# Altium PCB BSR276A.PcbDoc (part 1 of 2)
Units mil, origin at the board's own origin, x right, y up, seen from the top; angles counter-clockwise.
Board outline 2517.71 x 2251 mil, 4 copper layers (Top Layer, Signal Layer 1, Signal Layer 2, Bottom Layer), stack 61.6 mil thick; 70 components, 21 nets, 118 pads, 66 vias.
Unrouted connection lines stored in the file: 1.
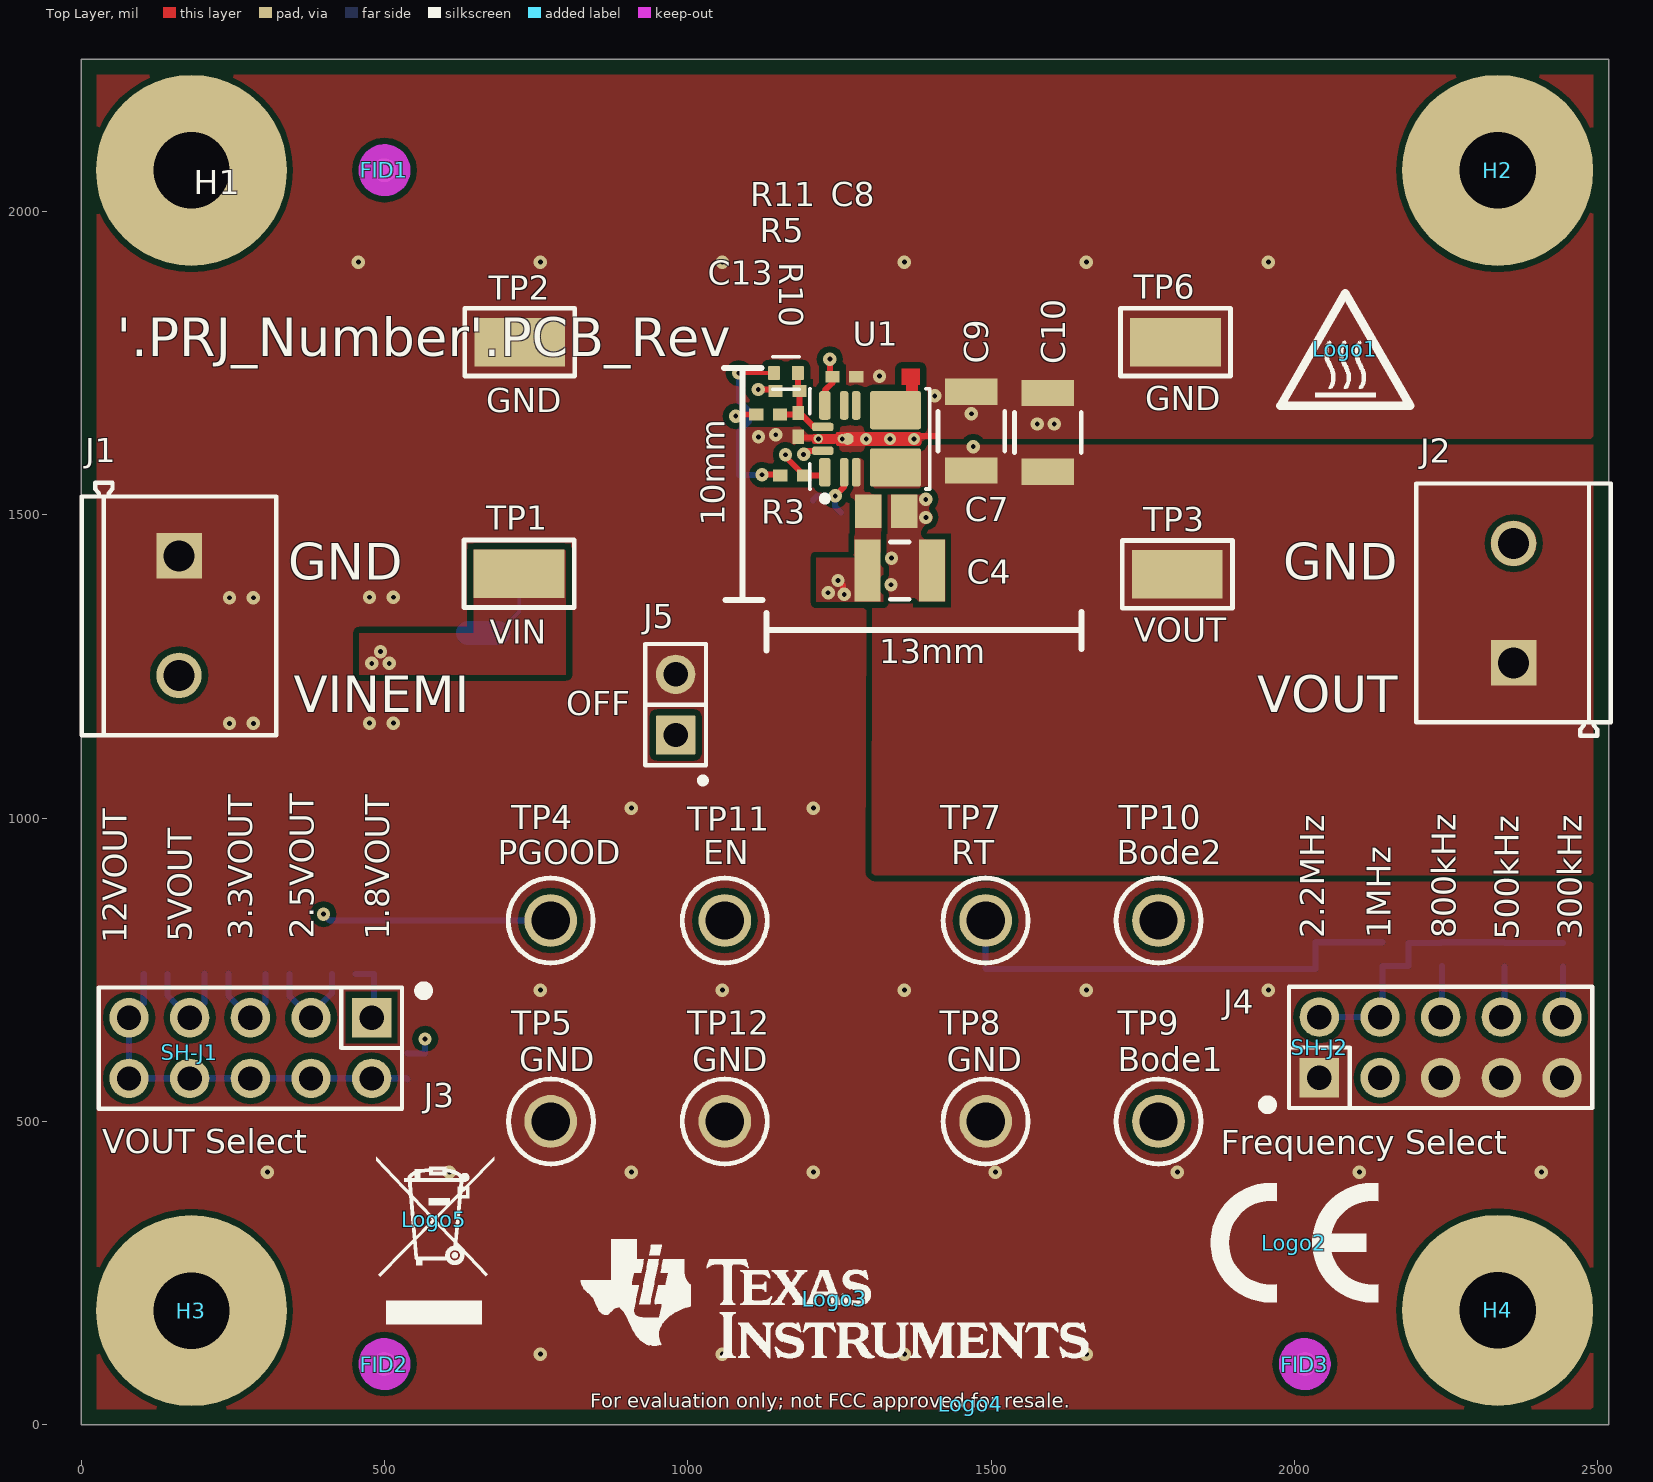
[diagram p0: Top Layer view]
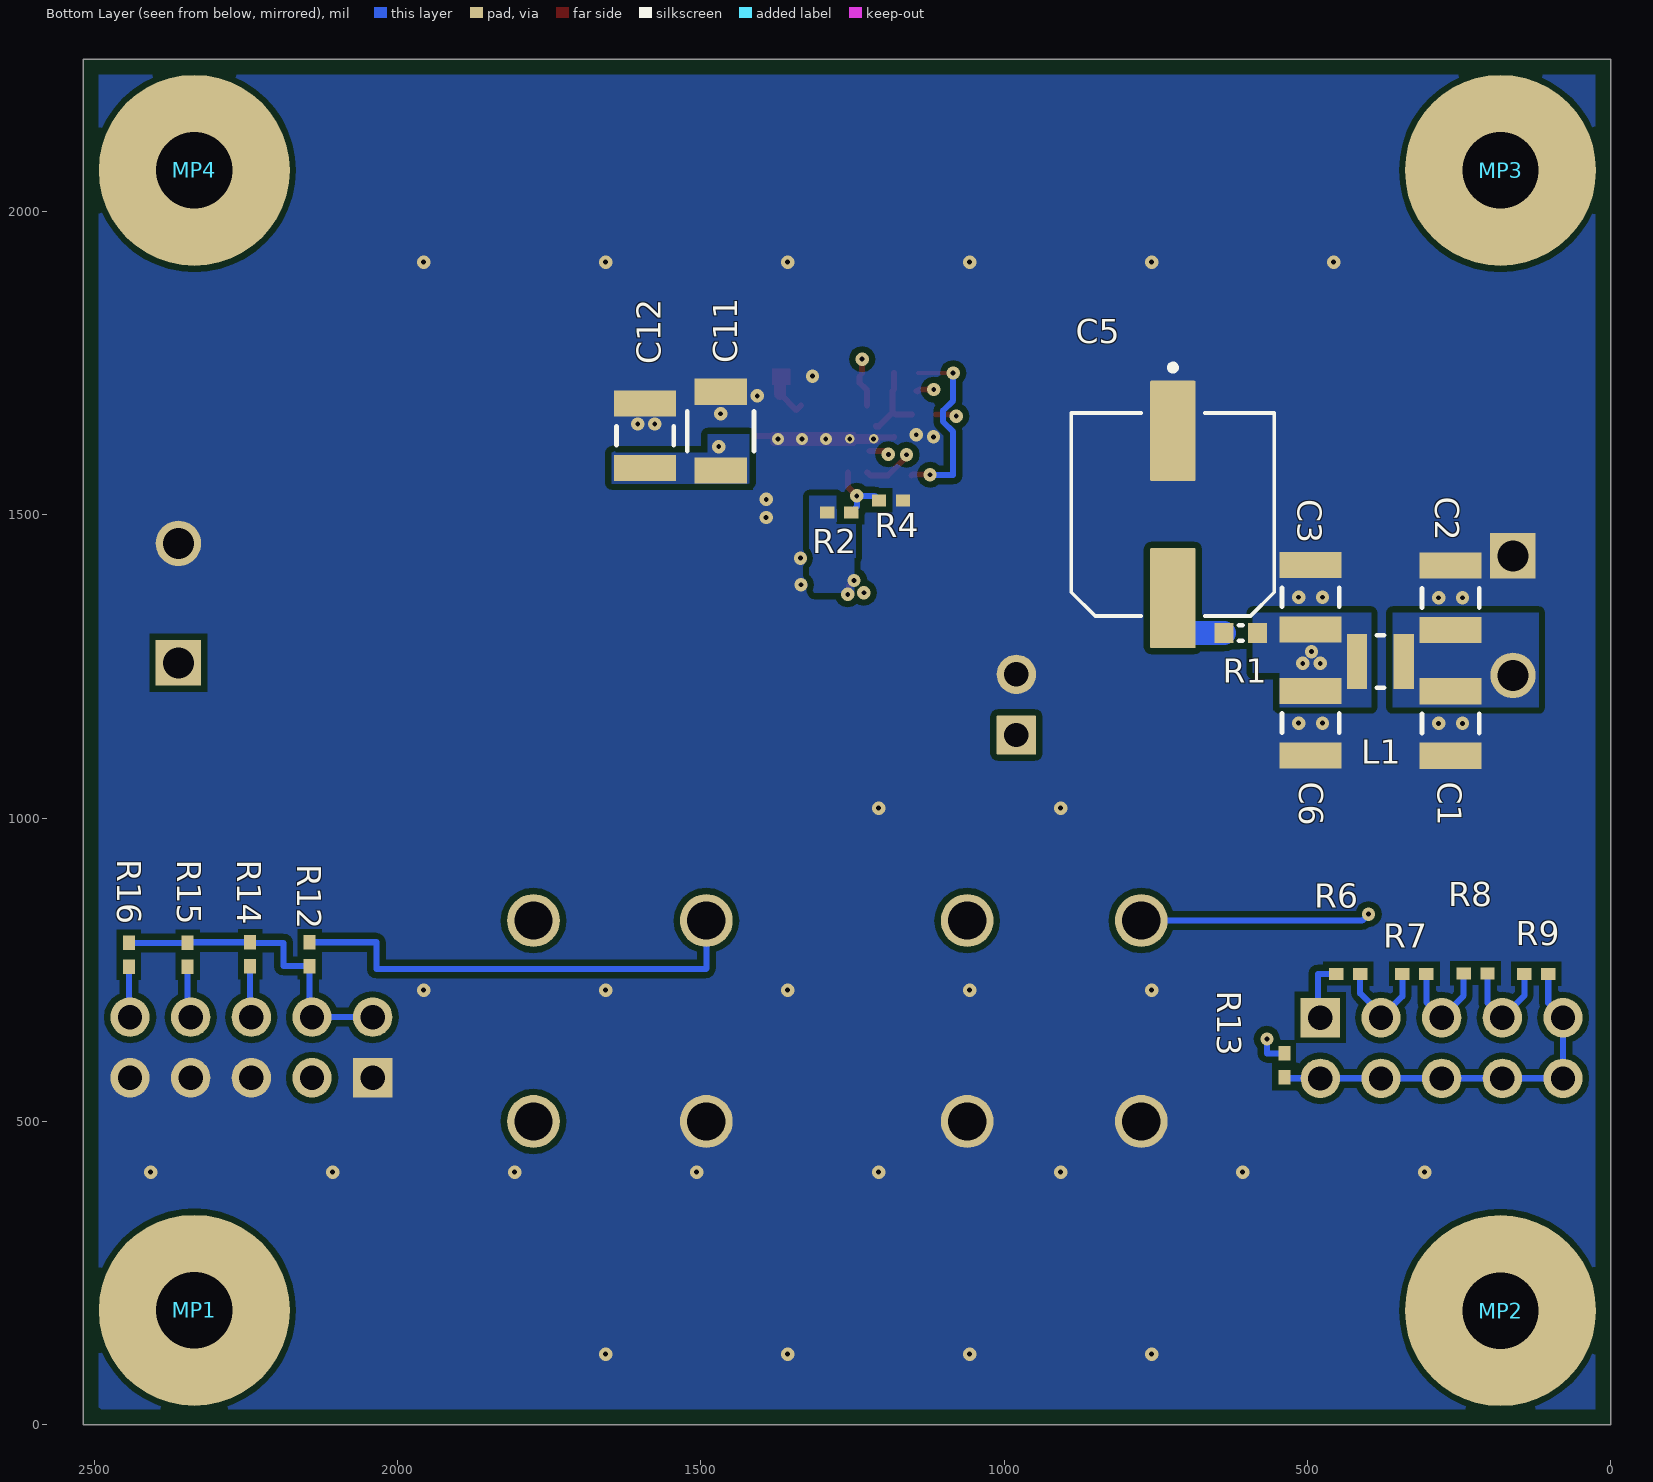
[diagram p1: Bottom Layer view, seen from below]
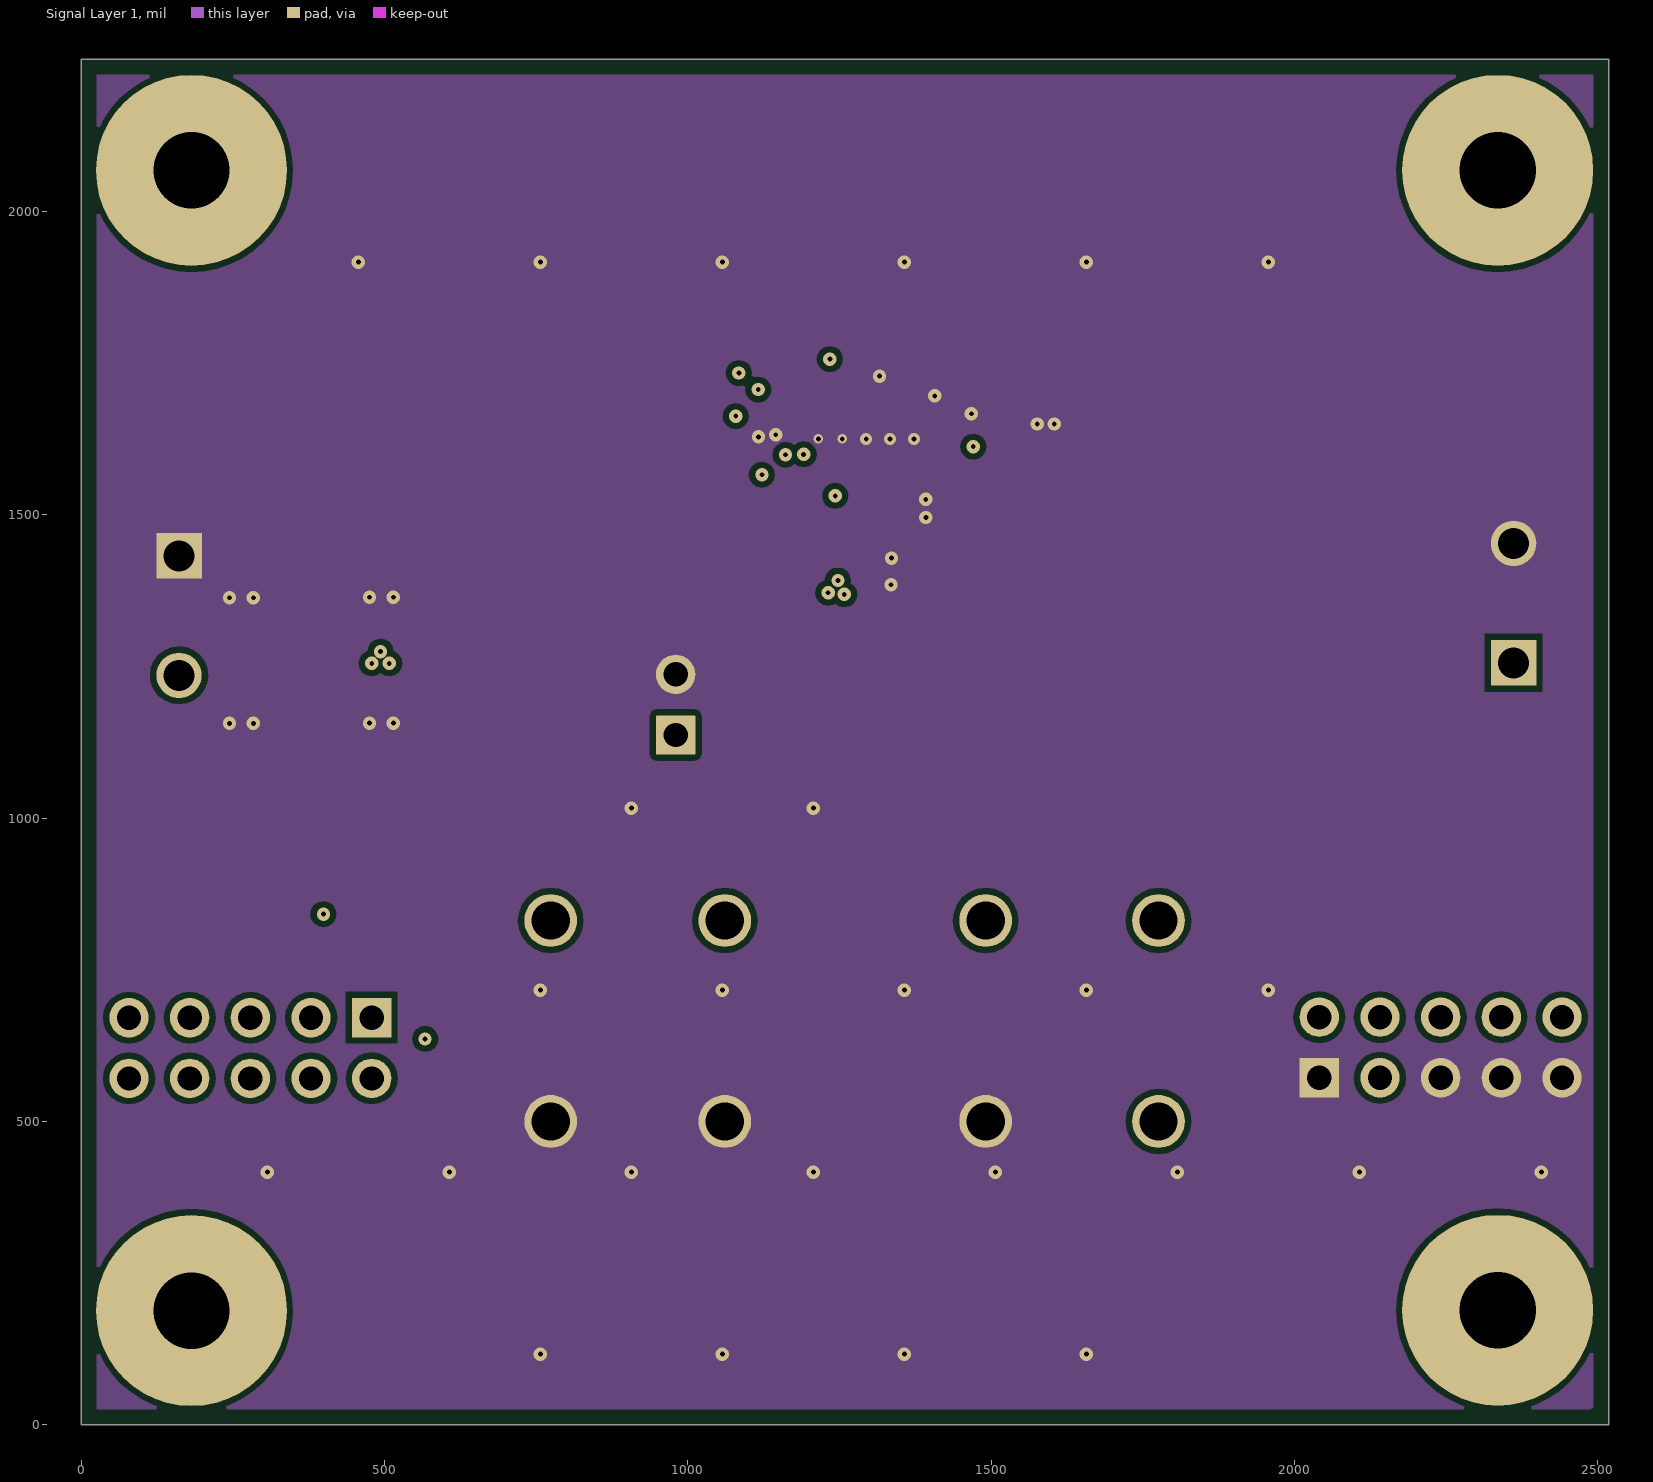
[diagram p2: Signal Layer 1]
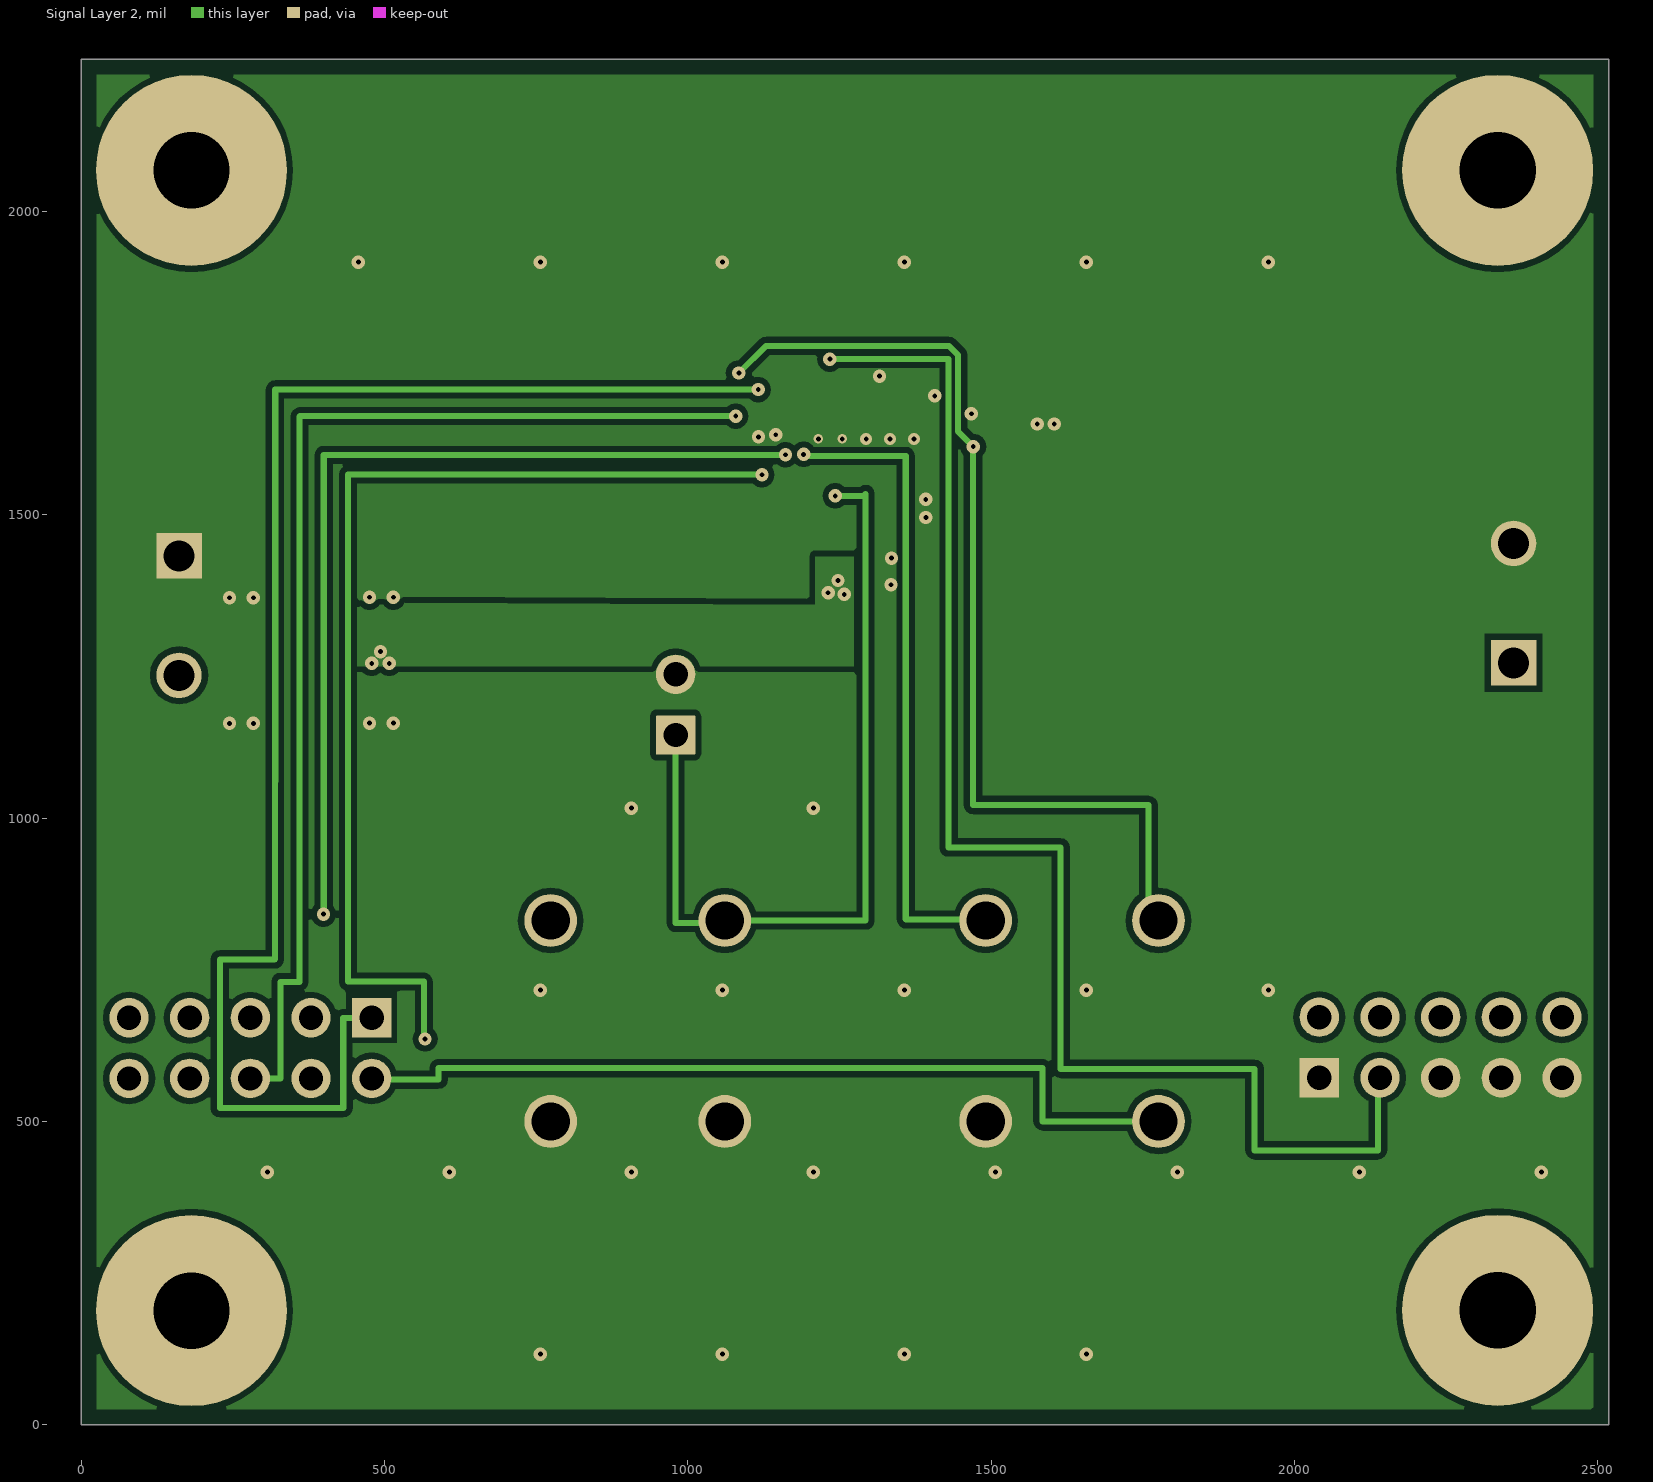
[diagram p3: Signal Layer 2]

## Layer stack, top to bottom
Top Solder: solder mask 0.4, Solder Resist, Dk 3.5
Top Layer: signal copper 1.4
Dielectric 1: prepreg 8, FR-4 High Tg, Dk 4.2
Signal Layer 1: signal copper 1.4
Dielectric 2: core 40, FR-4 High Tg, Dk 4.2
Signal Layer 2: signal copper 1.4
Dielectric 3: prepreg 8, FR-4 High Tg, Dk 4.2
Bottom Layer: signal copper 1.4
Bottom Solder: solder mask 0.4, Solder Resist, Dk 3.5

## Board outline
0,0 2517.71,0 2517.71,2251 2517.69,2250.98 0,2250.98

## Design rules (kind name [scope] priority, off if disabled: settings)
AcuteAngle [All] p1: minimum=4.50000000000000E+0001 checktracksonly=FALSE
AssemblyTestPointUsage [All] p1: valid=2
BoardOutlineClearance BoardOutlineClearance_MountingHoles [OnCopper and InComponentClass('Mounting Holes')] p1: gap=39.37 ignorepadtopadclearanceinfootprint=FALSE
BoardOutlineClearance BoardOutlineClearance_Poly [OnCopper and IsPoly] p2: gap=25 ignorepadtopadclearanceinfootprint=FALSE
BoardOutlineClearance [OnCopper and Not InComponentClass('Logo') and not InComponentClass('FiducialMark') and not InRegion(1000,500,4000,800) and not InPoly] p3: gap=40 ignorepadtopadclearanceinfootprint=FALSE
Clearance Clearance_Keepouts [((IsTrack Or IsArc) And Not InPoly) And IsFree and IsKeepOut vs ((IsTrack Or IsArc) And Not InPoly) And IsFree and IsKeepOut] p1: gap=0 ignorepadtopadclearanceinfootprint=FALSE
Clearance Clearance_Poly [InPolygon] p2: gap=10 ignorepadtopadclearanceinfootprint=TRUE
Clearance Clearance_FiducialMark [IsKeepOut and InComponentClass('FiducialMark') vs IsPad and InComponentClass('FiducialMark')] p3: gap=0 ignorepadtopadclearanceinfootprint=FALSE
Clearance [All] p4: gap=5.91 ignorepadtopadclearanceinfootprint=TRUE except(7.87: Text-Text Text-Hole)
ComponentClearance ComponentClearance_MountingHoles_FiducialMarks [InComponentClass('Mounting Holes') vs InComponentClass('FiducialMark')] p1: gap=50 collisioncheckmode=3 verticalgap=10 showdistances=FALSE
ComponentClearance ComponentClearance_Shunt [InComponentClass('Header') vs InComponentClass('Shunt')] p2: gap=0 collisioncheckmode=3 verticalgap=0 showdistances=FALSE
ComponentClearance ComponentClearance_Logo [InComponentClass('Logo')] p3: gap=30 collisioncheckmode=3 verticalgap=10 showdistances=FALSE
ComponentClearance ComponentClearance_ScrewToNut [(HasFootprint('NY PMS 440 0025 PH')) vs (HasFootprint('Keystone_1902C'))] p4: gap=5 collisioncheckmode=3 verticalgap=10 showdistances=FALSE
ComponentClearance ComponentClearance_MountingHoles [InComponentClass('Mounting Holes')] p5: gap=100 collisioncheckmode=3 verticalgap=100000 showdistances=FALSE
ComponentClearance ComponentClearance_SmallPassives [HasFootprint('0201*') or HasFootprint('0402*') or HasFootprint('0508') or HasFootprint('0603*') or HasFootprint('0612') or HasFootprint('0805*') or HasFootprint('0815*') or HasFootprint('0830*') or HasFootprint('1206*') or HasFootprint('1210*') or HasFootprint('1808*') or HasFootprint('1812*') or HasFootprint('1825*') or HasFootprint('2010*') or HasFootprint('2220*') or HasFootprint('2225*') or HasFootprint('2512*') or HasFootprint('2728*') or HasFootprint('3518*') vs HasFootprint('0201*') or HasFootprint('0402*') or HasFootprint('0508') or HasFootprint('0603*') or HasFootprint('0612') or HasFootprint('0805*') or HasFootprint('0815*') or HasFootprint('0830*') or HasFootprint('1206*') or HasFootprint('1210*') or HasFootprint('1808*') or HasFootprint('1812*') or HasFootprint('1825*') or HasFootprint('2010*') or HasFootprint('2220*') or HasFootprint('2225*') or HasFootprint('2512*') or HasFootprint('2728*') or HasFootprint('3518*')] p6: gap=14.96 collisioncheckmode=3 verticalgap=10 showdistances=FALSE
ComponentClearance ComponentClearance_THtoSMT [IsThruComponent vs IsSMTComponent] p7: gap=30 collisioncheckmode=3 verticalgap=30 showdistances=FALSE
ComponentClearance ComponentClearance_THtoTH [IsThruComponent vs IsThruComponent] p8: gap=20 collisioncheckmode=3 verticalgap=30 showdistances=FALSE
ComponentClearance [All] p9: gap=8 collisioncheckmode=3 verticalgap=10 showdistances=FALSE
DiffPairsRouting [All] p1: maxlimit=100 minlimit=10 mostfreqgap=10 substack1={4869F302-31FF-4282-8A62-242DEF238AA7} toplayer_{4869f302-31ff-4282-8a62-242def238aa7}_minwidth=15 toplayer_{4869f302-31ff-4282-8a62-242def238aa7}_maxwidth=15 toplayer_{4869f302-31ff-4282-8a62-242def238aa7}_prefwidth=15 midlayer1_{4869f302-31ff-4282-8a62-242def238aa7}_minwidth=15 midlayer1_{4869f302-31ff-4282-8a62-242def238aa7}_maxwidth=15 midlayer1_{4869f302-31ff-4282-8a62-242def238aa7}_prefwidth=15 midlayer2_{4869f302-31ff-4282-8a62-242def238aa7}_minwidth=15 midlayer2_{4869f302-31ff-4282-8a62-242def238aa7}_maxwidth=15 midlayer2_{4869f302-31ff-4282-8a62-242def238aa7}_prefwidth=15 bottomlayer_{4869f302-31ff-4282-8a62-242def238aa7}_minwidth=15 bottomlayer_{4869f302-31ff-4282-8a62-242def238aa7}_maxwidth=15 bottomlayer_{4869f302-31ff-4282-8a62-242def238aa7}_prefwidth=15 toplayer_minwidth=15 toplayer_maxwidth=15 toplayer_prefwidth=15 midlayer1_minwidth=15 midlayer1_maxwidth=15 midlayer1_prefwidth=15 midlayer2_minwidth=15 midlayer2_maxwidth=15 midlayer2_prefwidth=15 bottomlayer_minwidth=15 bottomlayer_maxwidth=15 bottomlayer_prefwidth=15 substack2={E3C2131B-1C0E-431A-9B14-2B1FF8BF5809} toplayer_{e3c2131b-1c0e-431a-9b14-2b1ff8bf5809}_minwidth=15 toplayer_{e3c2131b-1c0e-431a-9b14-2b1ff8bf5809}_maxwidth=15 toplayer_{e3c2131b-1c0e-431a-9b14-2b1ff8bf5809}_prefwidth=15 midlayer1_{e3c2131b-1c0e-431a-9b14-2b1ff8bf5809}_minwidth=15 midlayer1_{e3c2131b-1c0e-431a-9b14-2b1ff8bf5809}_maxwidth=15 midlayer1_{e3c2131b-1c0e-431a-9b14-2b1ff8bf5809}_prefwidth=15 midlayer2_{e3c2131b-1c0e-431a-9b14-2b1ff8bf5809}_minwidth=15 midlayer2_{e3c2131b-1c0e-431a-9b14-2b1ff8bf5809}_maxwidth=15 midlayer2_{e3c2131b-1c0e-431a-9b14-2b1ff8bf5809}_prefwidth=15 bottomlayer_{e3c2131b-1c0e-431a-9b14-2b1ff8bf5809}_minwidth=15 bottomlayer_{e3c2131b-1c0e-431a-9b14-2b1ff8bf5809}_maxwidth=15 bottomlayer_{e3c2131b-1c0e-431a-9b14-2b1ff8bf5809}_prefwidth=15 substack3={6311EC87-DE6E-4A89-91EC-D127DB06BA4F} toplayer_{6311ec87-de6e-4a89-91ec-d127db06ba4f}_minwidth=15 toplayer_{6311ec87-de6e-4a89-91ec-d127db06ba4f}_maxwidth=15 toplayer_{6311ec87-de6e-4a89-91ec-d127db06ba4f}_prefwidth=15 midlayer1_{6311ec87-de6e-4a89-91ec-d127db06ba4f}_minwidth=15 midlayer1_{6311ec87-de6e-4a89-91ec-d127db06ba4f}_maxwidth=15 midlayer1_{6311ec87-de6e-4a89-91ec-d127db06ba4f}_prefwidth=15 midlayer2_{6311ec87-de6e-4a89-91ec-d127db06ba4f}_minwidth=15 midlayer2_{6311ec87-de6e-4a89-91ec-d127db06ba4f}_maxwidth=15 midlayer2_{6311ec87-de6e-4a89-91ec-d127db06ba4f}_prefwidth=15 bottomlayer_{6311ec87-de6e-4a89-91ec-d127db06ba4f}_minwidth=15 bottomlayer_{6311ec87-de6e-4a89-91ec-d127db06ba4f}_maxwidth=15 bottomlayer_{6311ec87-de6e-4a89-91ec-d127db06ba4f}_prefwidth=15 substack4={011EBE24-0305-46D9-879A-9FB90939BB7C} toplayer_{011ebe24-0305-46d9-879a-9fb90939bb7c}_minwidth=15 toplayer_{011ebe24-0305-46d9-879a-9fb90939bb7c}_maxwidth=15 toplayer_{011ebe24-0305-46d9-879a-9fb90939bb7c}_prefwidth=15 midlayer1_{011ebe24-0305-46d9-879a-9fb90939bb7c}_minwidth=15 midlayer1_{011ebe24-0305-46d9-879a-9fb90939bb7c}_maxwidth=15 midlayer1_{011ebe24-0305-46d9-879a-9fb90939bb7c}_prefwidth=15 midlayer2_{011ebe24-0305-46d9-879a-9fb90939bb7c}_minwidth=15 midlayer2_{011ebe24-0305-46d9-879a-9fb90939bb7c}_maxwidth=15 midlayer2_{011ebe24-0305-46d9-879a-9fb90939bb7c}_prefwidth=15 bottomlayer_{011ebe24-0305-46d9-879a-9fb90939bb7c}_minwidth=15 bottomlayer_{011ebe24-0305-46d9-879a-9fb90939bb7c}_maxwidth=15 bottomlayer_{011ebe24-0305-46d9-879a-9fb90939bb7c}_prefwidth=15 maxuncoupledlength=1000
FabricationTestPointUsage TestPointUsage [All] p1: valid=2 allowmultiple=FALSE
FabricationTestpoint Testpoint [All] p1: side=3 testpointundercomponent=TRUE minsize=40 maxsize=100 preferedsize=60 minholesize=0 maxholesize=40 preferedholesize=32 testpointgrid=1 allowsidetop=TRUE allowsidebottom=TRUE usegrid=TRUE gridtolerance=0.01
FanoutControl Fanout_LCC [IsLCC] p1: bgadir=Out bgaviamode=Centered fanoutstyle=Auto fanoutdirection=Alternating viagrid=1 // Fanout_LCC (Default Rule)
FanoutControl Fanout_BGA [IsBGA] p2: bgadir=Out bgaviamode=Centered fanoutstyle=Auto fanoutdirection=Alternating viagrid=1 // Fanout_BGA (Default Rule)
FanoutControl Fanout_Default [All] p4: bgadir=Out bgaviamode=Centered fanoutstyle=Auto fanoutdirection=Alternating viagrid=1 // Fanout_Default (Default Rule)
FanoutControl Fanout_Small [(CompPinCount < 5)] p5: bgadir=Out bgaviamode=Centered fanoutstyle=Auto fanoutdirection=OutThenIn viagrid=1 // Fanout_Small (Default Rule)
HoleSize [All] p1: absolutevalues=TRUE maxlimit=251 minlimit=7.87 maxpercent=80.000 minpercent=20.000
MinimumAnnularRing MinimumAnnularRing_ThermalPadVias [IsVia and InAnyComponent] p1: minimumring=5.91
MinimumAnnularRing [All] p2: minimumring=5.9
MinimumSolderMaskSliver MinimumSolderMaskSliver_Logo [InComponentClass('Logo') vs InComponentClass('Logo')] p1: minsoldermaskwidth=0.7
MinimumSolderMaskSliver [All] p2: minsoldermaskwidth=3.94
PlaneConnect [All] p1: planeconnectstyle=Relief reliefexpansion=10 reliefentries=4 reliefconductorwidth=10 reliefairgap=10
PolygonConnect [All] p1: connectstyle=Direct reliefconductorwidth=10 reliefentries=4 polygonreliefangle="90 Angle" airgapwidth=10
RoutingLayers [All] p1: top layer_v5=TRUE mid layer 1_v5=FALSE mid layer 2_v5=FALSE bottom layer_v5=TRUE
RoutingVias ThermalPadVias [IsVia and InAnyComponent] p1: holewidth=7.87 width=19.68 viastyle="Through Hole" minholewidth=7.87 minwidth=19.68 maxholewidth=12.99 maxwidth=23.62
RoutingVias [All] p2: holewidth=16 width=34 viastyle="Through Hole" minholewidth=7.87 minwidth=24 maxholewidth=40 maxwidth=65
SilkToBoardRegionClearance [Not ((IsComment or IsDesignator) And (Hide <> 'False')) and not InRegion(1000,500,4000,800)] p1:
SilkToSilkClearance SilkToSilkClearance_Pb-FreeLogo [(HasFootprint('Pb-Free_Overlay_Medium') OR HasFootprint('Pb-Free_Overlay_Small')) vs (HasFootprint('Pb-Free_Overlay_Medium') OR HasFootprint('Pb-Free_Overlay_Small'))] p1: silktosilkclearance=0
SilkToSilkClearance [All] p2: silktosilkclearance=3.94
SilkToSolderMaskClearance SilkToComponentPadClearance [(IsPad or IsFill or IsRegion) and InAnycomponent] p1: minsilkscreentomaskgap=5 clearancetoexposedcopper=TRUE
SilkToSolderMaskClearance "Silk to Solder Mask Opening" [All] p2: minsilkscreentomaskgap=3.94 clearancetoexposedcopper=FALSE
SolderMaskExpansion [All] p1: expansion=1.97 istentingtop=FALSE
UnRoutedNet [All] p1: checkbadconnections=TRUE
Width [All] p1: maxlimit=100 minlimit=6 preferedwidth=10 substack1={4869F302-31FF-4282-8A62-242DEF238AA7} substack2={E3C2131B-1C0E-431A-9B14-2B1FF8BF5809} substack3={6311EC87-DE6E-4A89-91EC-D127DB06BA4F} substack4={011EBE24-0305-46D9-879A-9FB90939BB7C} checkconnectedcopper=TRUE
13 further rules are at their usual default settings.

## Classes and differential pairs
component class AssemblyNote: ZZ1 ZZ2 ZZ3 ZZ4
component class FiducialMark: FID1 FID2 FID3
component class BSR276A_Hardware: FID1 FID2 FID3 H1 H2 H3 H4 Logo1 Logo2 Logo3 Logo4 Logo5 MP1 MP2 MP3 MP4 SH-J1 SH-J2 ZZ1 ZZ2 ZZ3 ZZ4
component class Logo: Logo3
component class "Mounting Holes": H1 H2 H3 H4
component class BSR276A: C1 C2 C3 C4 C5 C6 C7 C8 C9 C10 C11 C12 C13 J1 J2 J3 J4 J5 L1 R1 R2 R3 R4 R5 R6 R7 R8 R9 R10 R11 R12 R13 R14 R15 R16 TP1 TP2 TP3 TP4 TP5 TP6 TP7 TP8 TP9 TP10 TP11 TP12 U1
component class Header: J3 J4 J5

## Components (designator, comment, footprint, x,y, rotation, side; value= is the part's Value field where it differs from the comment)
C1 "CGA6N3X7R2A225K230AB" 1210_250L 264.24,1156 r270 bottom value=2.2uF
C2 "CGA6N3X7R2A225K230AB" 1210_250L 264.24,1363 r90 bottom value=2.2uF
C3 "CGA6N3X7R2A225K230AB" 1210_250L 495,1364.01 r90 bottom value=2.2uF
C4 "CGA6N3X7R2A225K230AB" 1210_250L 1349.42,1407.93 r0 top value=2.2uF
C5 "875075955001" FP-875075955001_SMT_CAP_8MM3_8MM3-MFG 722,1500.35 r270 bottom value=10µF
C6 "CGA6N3X7R2A225K230AB" 1210_250L 495,1156.38 r270 bottom value=2.2uF
C7 "885012207128" 0805L 1327.23,1505.64 r0 top value=0.1uF
C8 "EMK105BJ105KVHF" 0402L 1258.28,1727.36 r180 top value=1uF
C9 "CGA6P1X7R1C226M250AC" 1210_280 1467.52,1637.8 r90 top value=22uF
C10 "CGA6P1X7R1C226M250AC" 1210_280 1593.5,1635.63 r90 top value=22uF
C11 "CGA6P1X7R1C226M250AC" 1210_280 1467.52,1637.79 r90 bottom value=22uF
C12 "GRM32EC70J107ME15L" 1210_270L 1592,1630.05 r90 bottom value=100uF
C13 "CGA2B2NP01H220J050BA" 0402L 1132.48,1664.86 r0 top value=22pF
FID1 "Fiducial" Fiducial10-20 500,2067.83 r0 top
FID2 "Fiducial" Fiducial10-20 500,100 r0 top
FID3 "Fiducial" Fiducial10-20 2017,100 r0 top
H1 "NY PMS 440 0025 PH" "NY PMS 440 0025 PH"#1 182,2067.57 r0 top
H2 "NY PMS 440 0025 PH" "NY PMS 440 0025 PH"#1 2335,2067.57 r0 top
H3 "NY PMS 440 0025 PH" "NY PMS 440 0025 PH"#2 182,188.57 r0 top
H4 "NY PMS 440 0025 PH" "NY PMS 440 0025 PH"#3 2334.65,188.57 r0 top
J1 "VIN" Phoenix_1729018 161.42,1333.66 r270 top
J2 "VOUT" Phoenix_1729018 2361.22,1354.33 r90 top
J3 "VOUT Select" CONN_PEC05DAAN 279,620.87 r180 top
J4 "Frequency Select" CONN_PEC05DAAN 2241,621.85 r0 top
J5 "OFF" Samtec_HTSW-102-07-G-S 980,1186.81 r90 top
L1 "74438324047" WE-MAPI_2512 380,1258 r0 bottom value=4.7uH
Logo1 "CAUTION HOT SURFACE" IEC_HotSurface_Small 2084,1772.64 r0 top
Logo2 "CE Mark" CE_Mark_5mm 2000,300 r0 top
Logo3 "Texas Instruments" TI_Stacked_Overlay_Small 1242.13,207.68 r0 top
Logo4 "FCC disclaimer" FCC_disclaimer 1466.41,33.46 r0 top
Logo5 "WEEE logo" WEEE_Minimum 582,337.6 r0 top
MP1 "1902D_Ndrill" FP-1902D_Ndrill_HEX_STANDOFF-MFG 2335,188.57 r180 bottom
MP2 "1902D_Ndrill" FP-1902D_Ndrill_HEX_STANDOFF-MFG 182,188.05 r180 bottom
MP3 "1902D_Ndrill" FP-1902D_Ndrill_HEX_STANDOFF-MFG 182,2067.57 r180 bottom
MP4 "1902D_Ndrill" FP-1902D_Ndrill_HEX_STANDOFF-MFG 2335,2067.57 r180 bottom
R1 "RMCF0603ZT0R00" 0603L 610.07,1305.13 r180 bottom value=0
R2 "CRCW0402255KFKED" 0402L 1272,1503.94 r0 bottom value=255k
R3 "CRCW040249K9FKED" 0402L 1172.24,1564.57 r0 top value=49.9k
R4 "CRCW040247K0JNED" 0402L 1186.63,1523.62 r180 bottom value=47k
R5 "CRCW04028K06FKED" 0402L 1164.37,1703.74 r0 top value=8.06k
R6 "CRCW04026K98FKED" 0402L 433,743.11 r0 bottom value=6.98k
R7 "CRCW04028K06FKED" 0402L 324,743.11 r0 bottom value=8.06k
R8 "CRCW040216K9FKED" 0402L 223,744.09 r0 bottom value=16.9k
R9 "CRCW040269K8FKED" 0402L 123,743.11 r0 bottom value=69.8k
R10 "CRCW040210K0FKED" 0402L 1182.09,1648.05 r90 top value=10.0k
R11 "RMCF0402ZT0R00" FP-RMCF0402ZT0R00_0402-MFG 1161.73,1733.52 r180 top value=0
R12 "CRCW04020000Z0ED" 0402L 2145,775.59 r90 bottom value=0
R13 "CRCW040210R0FKED" 0402L 538.39,592.61 r90 bottom value=10.0
R14 "CRCW040220K0FKED" 0402L 2243,775.59 r90 bottom value=20.0k
R15 "CRCW040233K2FKED" 0402L 2346,774.61 r90 bottom value=33.2k
R16 "CRCW040254K9FKED" 0402L 2443,774.61 r90 bottom value=54.9k
SH-J1 "881545-2" TE_881545-2 179,613.71 r90 top
SH-J2 "881545-2" TE_881545-2 2042,622.05 r90 top
TP1 "VIN" Keystone_5019 722,1402.56 r0 top
TP2 "GND" Keystone_5019 723,1784.45 r0 top
TP3 "VOUT" Keystone_5019 1807,1401.57 r0 top
TP4 "PGOOD" Keystone5012 774,831 r0 top
TP5 "GND" Keystone5011#1 774.61,500 r0 top
TP6 "GND" Keystone_5019 1804,1784.45 r0 top
TP7 "RT" Keystone5012 1491,831 r0 top
TP8 "GND" Keystone5011#2 1491,500 r0 top
TP9 "Bode1" Keystone5012 1776,500 r0 top
TP10 "Bode2" Keystone5012 1776,831 r0 top
TP11 "EN" Keystone5012 1061,831 r0 top
TP12 "GND" Keystone5011#2 1061,500 r0 top
U1 "TPSM33625FRDNR" RDN0011A-MFG 1303.15,1625 r90 top
ZZ1 "This Assembly Note is for PCB labels only" AssemblyNoteLabel 185,3938 r0 top
ZZ2 "These assemblies are ESD sensitive, ESD precautions shall be observed." AssemblyNote 185,3829.11 r0 top
ZZ3 "These assemblies must be clean and free from flux and all contaminants. Use of no clean flux is not acceptable." AssemblyNote 185,3740.56 r0 top
ZZ4 "These assemblies must comply with workmanship standards IPC-A-610 Class 2, unless otherwise specified." AssemblyNote 185,3652 r0 top

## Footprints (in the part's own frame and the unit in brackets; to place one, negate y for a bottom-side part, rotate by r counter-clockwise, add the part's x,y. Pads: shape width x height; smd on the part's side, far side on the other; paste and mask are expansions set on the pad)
0402L [mm] "0402 from SM-752 data"
  rect 0.6x0.5 smd: 1(-0.5,0) 2(0.5,0)
  body extent -0.55,-0.3 0.55,0.3, height 0.6
0603L [mm] "0603 from SM-752 data"
  rect 0.8x0.85 smd: 1(-0.7,0) 2(0.7,0)
  silkscreen extent -0.07,-0.33 0.07,0.33, body extent -0.87,-0.47 0.87,0.47, height 1
0805L [mm] "0805 from SM-752 data"
  rect 1.1x1.4 smd: 1(-0.75,0) 2(0.75,0)
  body extent -1.1,-0.72 1.1,0.72, height 1.45
1210_250L [mm] "1210"
  rect 1.1x2.6 smd: 1(-1.35,0) 2(1.35,0)
  silkscreen extent -0.4,-1.2 0.4,1.2, body extent -1.7,-1.35 1.7,1.35, height 2.5
1210_270L [mm] "1210"
  rect 1.1x2.6 smd: 1(-1.35,0) 2(1.35,0)
  silkscreen extent -0.4,-1.2 0.4,1.2, body extent -1.7,-1.35 1.7,1.35, height 2.7
1210_280 [mm] "SMD, 2-Leads, Body 3.6x2.8mm, Height 2.8mm"
  rect 1.1x2.2 smd: 1(-1.65,0) 2(1.65,0)
  silkscreen extent -0.84,-1.4 0.84,1.4, body extent -1.8,-1.4 1.8,1.4, height 2.8
AssemblyNote [mil] "Assembly Note"
AssemblyNoteLabel [mil] "Assembly Note for PCB Labels"
CE_Mark_5mm [mil] "Minimum text height for CE Mark"
  silkscreen extent -138,-98 138,98
CONN_PEC05DAAN [mm] "SULLINS"
  rect 1.65x1.65 hole 1.016 mask+0: 1(-5.08,-1.27)
  round 1.65 hole 1.016 mask+0: 2(-5.08,1.27) 3(-2.54,-1.27) 4(-2.54,1.27) 5(0,-1.27) 6(0,1.27) 7(2.54,-1.27) 8(2.54,1.27) 9(5.08,-1.27) 10(5.08,1.27)
  silkscreen extent -7.45,-2.6 6.35,2.54, body extent -6.35,-2.54 6.35,2.54, height 8.38
FCC_disclaimer [mil]
Fiducial10-20 [mm]
  round 1 smd mask+0.5: 1(0,0)
  Top Layer keep-out circle w1.178: c0,0 r0.5
FP-1902D_Ndrill_HEX_STANDOFF-MFG [mil]
  body extent -144,-125 144,125, height 765
FP-875075955001_SMT_CAP_8MM3_8MM3-MFG [mm]
  rrect5% 4.2x1.9 smd paste+0 mask+0: 1(-3.5,0) 2(3.5,0)
  silkscreen extent -6.27,-4.25 4.25,4.25, body extent -4.5,-4.15 4.5,4.15, height 12
FP-RMCF0402ZT0R00_0402-MFG [mm]
  rrect20% 0.5x0.6 smd paste+0 mask+0: 1(-0.5,0) 2(0.5,0)
  silkscreen extent -0.55,-0.67 0.55,0.67, body extent -0.85,-0.4 0.85,0.4, height 0.25
IEC_HotSurface_Small [mil]
  silkscreen extent -107,-93 107,92
Keystone5011#1 [mil] "Keystone Multipurpose loops"
  round 87 hole 63: 1(-0.61,0)
  silkscreen extent -70,-70 70,70, body extent -63,-63 63,62, height 319
Keystone5011#2 [mil] "Keystone Multipurpose loops"
  round 87 hole 63: 1(0,0)
  silkscreen extent -70,-70 70,70, body extent -63,-63 63,62, height 319
Keystone5012 [mil] "Keystone Multipurpose loops"
  round 87 hole 63: 1(0,0)
  silkscreen extent -70,-70 70,70, body extent -63,-63 63,62, height 319
Keystone_5019 [mm] "Test Point, Miniature, SMT"
  rect 3.8x2.03 smd: 1(0,0)
  silkscreen extent -2.31,-1.42 2.31,1.42, body extent -1.9,-1.02 1.9,1.02, height 2.29
"NY PMS 440 0025 PH"#1 [mm] "4-40 nylon screw and mounting hole"
  round 8 hole 3.2: 1(0,0)
  body extent -3.3,-3.3 3.3,3.3, height 2.69
"NY PMS 440 0025 PH"#2 [mm] "4-40 nylon screw and mounting hole"
  round 8 hole 3.2: 1(0,-0.013)
  body extent -3.3,-3.3 3.3,3.3, height 2.69
"NY PMS 440 0025 PH"#3 [mm] "4-40 nylon screw and mounting hole"
  round 8 hole 3.2: 1(0.009,0)
  body extent -3.3,-3.3 3.3,3.3, height 2.69
Phoenix_1729018 [mm] "Phoenix Contact"
  rect 1.905x1.905 hole 1.3: 1(-2.5,0)
  round 1.9 hole 1.3: 2(2.5,0)
  silkscreen extent -5.56,-4.08 5.01,4.07, body extent -5.56,-4.08 5.01,4.07, height 10
RDN0011A-MFG [mm]
  rrect42% 1.2x0.475 smd paste-1000 mask-1000: 1(-1.4,1.962) 8(1.4,1.962)
  rrect57% 1.2x0.35 smd paste-1000 mask-1000: 2(-1.4,1.15) 3(-1.4,0.65) 6(1.4,0.65) 7(1.4,1.15)
  rrect13% 1.6x2.15 smd paste-1000 mask-1000: 4(-1.2,-1) 5(1.2,-1)
  rrect57% 0.35x0.9 smd paste-1000 mask-1000: 9(0.5,2.05) 11(-0.5,2.05)
  round 0.504 smd paste-1000 mask-1000: 10(0,1.005)
  Top Layer region: -0.2,2.4 -0.187,2.45 -0.15,2.487 -0.1,2.5 -0.1,2.5 0.1,2.5 0.15,2.487 0.187,2.45 0.2,2.4 0.2,2.4 0.2,1.515 0.203,1.5 0.212,1.487 0.225,1.478 0.24,1.475 0.24,1.475 0.24,1.475 0.26,1.47 0.275,1.455 0.28,1.435 0.28,1.435 0.28,-1.975 0.267,-2.025 0.23,-2.062 0.18,-2.075 0.18,-2.075 -0.18,-2.075 -0.23,-2.062 -0.267,-2.025 -0.28,-1.975 -0.28,-1.975 -0.28,1.435 -0.275,1.455 -0.26,1.47 -0.24,1.475 -0.24,1.475 -0.24,1.475 -0.225,1.478 -0.212,1.487 -0.203,1.5 -0.2,1.515 -0.2,1.515
  silkscreen extent -2.62,-2.42 2.1,2.6, body extent -2.1,-2.4 2.1,2.6, height 0.25
Samtec_HTSW-102-07-G-S [mm] "Samtec 100mil, 1x2, 230 mil above insulator"
  rrect6% 1.65x1.65 hole 1.016: 1(-1.27,0)
  round 1.65 hole 1.016: 2(1.27,0)
  silkscreen extent -3.3,-1.27 2.54,1.27, body extent -2.54,-1.27 2.54,1.27, height 8.38
TE_881545-2 [mil] "TE"
  round 1 on Mech3: 0(0,0)
  body extent -99,-49 99,49, height 530
TI_Stacked_Overlay_Small [mil]
  silkscreen extent -418,-98 418,98
WE-MAPI_2512 [mm] "SMD, 2-Leads, Body 2.5x2mm"
  rect 0.85x2.3 smd: 1(-0.975,0) 2(0.975,0)
  silkscreen extent -0.15,-1.1 0.15,1.1, body extent -1.25,-1 1.25,1, height 1.2
WEEE_Minimum [mil] "WEEElie bin"
  silkscreen extent -95,-172 99,104

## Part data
C1 C2 C3 C4 C6: library part CMP-0009152-2, "CAP, CERM, 2.2 uF, 100 V, +/- 10%, X7R, AEC-Q200 Grade 1,", Cap_Case=1210_250, Manufacturer=TDK, Supplier Part Number 1=445-5866-1-ND, TempCo=X7R, Tolerance_%=10%, Value1="0.00173 ohm", Value2=100V, ValueDisplayed=2.2uF
C5: library part CMP-0097784-1, "10µF 100V Aluminum - Polymer Capacitors Radial, Can - SMD 45mOhm 2000 Hrs @ 105°C", Digikey Part Number=732-11987-1-ND, Leakage Current=200uA, Manufacturer="Wurth Electronics", Mouser Part Number=710-875075955001, Operating Temperature Range="-55°C to +105°C", Tolerance_%=20%, ValueDisplayed=10uF
C7: library part CMP-0750058-1, "CAP, CERM, 0.1 µF, 100 V,+/- 10%, X7R, 0805", Cap_Case=0805, Manufacturer="Wurth Elektronik", TempCo=X7R, Tolerance_%=10%, Value2=100V, ValueDisplayed=0.1µF
C8: library part CMP-0006347-2, "CAP, CERM, 1 uF, 16 V, +/- 10%, X5R, 0402", Cap_Case=0402, Manufacturer="Taiyo Yuden", Supplier Part Number 1=587-3709-2-ND, TempCo=X5R, Tolerance_%=10%, Value1=Unknown, Value2=16V, ValueDisplayed=1uF
C9 C10 C11: library part CMP-0009154-2, "CAP, CERM, 22 uF, 16 V, +/- 20%, X7R, AEC-Q200 Grade 1, 1210", Cap_Case=1210_280, Manufacturer=TDK, Supplier Part Number 1=445-5723-1-ND, TempCo=X7R, Tolerance_%=20%, Value1="0.002582 ohm", Value2=16V, ValueDisplayed=22uF
C12: library part CMP-0083812-2, "CAP, CERM, 100 µF, 6.3 V,+/- 20%, X7S, 1210", Cap_Case=1210, Manufacturer=MuRata, Supplier Part Number 1=490-10530-1-ND, TempCo=X7S, Tolerance_%=20%, Value2=6.3V, ValueDisplayed=100µF
C13: library part CMP-0006311-2, "CAP, CERM, 22 pF, 50 V, +/- 5%, C0G/NP0, AEC-Q200 Grade 1, 0402", Cap_Case=0402, Manufacturer=TDK, Supplier Part Number 1=445-12130-1-ND, TempCo=C0G/NP0, Tolerance_%=5%, Value1=Unknown, Value2=50V, ValueDisplayed=22pF
FID1 FID2 FID3: library part CMP-0077181-1, "Fiducial mark.  There is nothing to buy or mount.", Manufacturer=N/A
H1 H2 H3 H4: library part CMP-0003617-1, "Machine Screw, Round, #4-40 x 1/4, Nylon, Philips panhead", Manufacturer="B&F Fastener Supply", Supplier Part Number 1=H542-ND
J1 J2: library part CMP-0055486-1, "TERM BLOCK 2POS 5mm, TH", Manufacturer="Phoenix Contact", PartNumber=1729018, Supplier Part Number 1=651-1729018
J3 J4: library part CMP-0054550-2, "Header, 100mil, 5x2, Tin, TH", Color=Black, Current_A=3A, Manufacturer="Sullins Connector Solutions", PartNumber=PEC05DAAN, Supplier Part Number 1=S2012E-05-ND, Voltage_V=1.8kV
J5: library part CMP-0075483-1, "Header, 100mil, 2x1, Gold, TH", Manufacturer=Samtec, PartNumber=HTSW-102-07-G-S, Supplier Part Number 1=SAM8736-ND
L1: library part CMP-0064146-1, "Inductor, Shielded, Powdered Iron, 4.7 uH, 1 A, 0.345 ohm, SMD", Manufacturer="Wurth Elektronik", Supplier Part Number 1=732-5685-1-ND, Value1="0.345 ohm", Value2=1A, ValueDisplayed=4.7uH
Logo1: library part CMP-0074837-2, "IEC 61010-1 Hot Surface Warning", Manufacturer="Texas Instruments"
Logo2: library part CMP-0074844-1
Logo3: library part CMP-0074838-1, "Texas Instrument Corporate Signature"
Logo4: library part CMP-0074847-1, "FCC_disclaimer"
Logo5: library part CMP-0074769-1
MP1 MP2 MP3 MP4: library part CMP-0090542-1, Digikey Part Number=36-1902D-ND, Manufacturer="Keystone Electronics", Mouser Part Number=534-1902D, Operating Temperature Range=to
R1: library part CMP-0023343-3, "RES, 0, 1%, 0.1 W, AEC-Q200 Grade 0, 0603", Manufacturer="Stackpole Electronics Inc", Power_W=100mW, Supplier Part Number 1=RMCF0603ZT0R00CT-ND, TempCo=ppm/C, Tolerance_%=1%, Value2=0.1W, Value_Code=0
R2: library part CMP-0026199-2, "RES, 255 k, 1%, 0.063 W, AEC-Q200 Grade 0, 0402", Manufacturer=Vishay-Dale, Power_W=63mW, Supplier Part Number 1=541-255KLCT-ND, TempCo="100 ppm/C", Tolerance_%=1%, Value2=0.063W, Value_Code=255k
R3: library part CMP-0026403-1, "RES, 49.9 k, 1%, 0.063 W, 0402", Manufacturer=Vishay-Dale, Power_W=63mW, Supplier Part Number 1=541-49.9KLCT-ND, TempCo="100 ppm/C", Tolerance_%=1%, Value2=0.063W, Value_Code=49k9, ValueDisplayed=49.9k
R4: library part CMP-0026935-3, "RES, 47 k, 5%, 0.063 W, AEC-Q200 Grade 0, 0402", Manufacturer=Vishay-Dale, Power_W=63mW, Supplier Part Number 1=541-47KJCT-ND, TempCo="200 ppm/C", Tolerance_%=5%, Value2=0.063W, Value_Code=47k0, ValueDisplayed=47k
R5 R7: library part CMP-0026588-2, "RES, 8.06 k, 1%, 0.063 W, AEC-Q200 Grade 0, 0402", Manufacturer=Vishay-Dale, Power_W=63mW, Supplier Part Number 1=541-8.06KLCT-ND, TempCo="100 ppm/C", Tolerance_%=1%, Value2=0.063W, Value_Code=8k06, ValueDisplayed=8.06k
R6: library part CMP-0026518-2, "RES, 6.98 k, 1%, 0.063 W, AEC-Q200 Grade 0, 0402", Manufacturer=Vishay-Dale, Power_W=63mW, Supplier Part Number 1=541-6.98KLCT-ND, TempCo="100 ppm/C", Tolerance_%=1%, Value2=0.063W, Value_Code=6k98, ValueDisplayed=6.98k
R8: library part CMP-0026042-3, "RES, 16.9 k, 1%, 0.063 W, AEC-Q200 Grade 0, 0402", Manufacturer=Vishay-Dale, Power_W=63mW, Supplier Part Number 1=541-16.9KLCT-ND, TempCo="100 ppm/C", Tolerance_%=1%, Value2=0.063W, Value_Code=16k9, ValueDisplayed=16.9k
R9: library part CMP-0026510-1, "RES, 69.8 k, 1%, 0.063 W, 0402", Manufacturer=Vishay-Dale, Power_W=63mW, Supplier Part Number 1=541-69.8KLCT-ND, TempCo="100 ppm/C", Tolerance_%=1%, Value2=0.063W, Value_Code=69k8, ValueDisplayed=69.8k
R10: library part CMP-0025958-3, "RES, 10.0 k, 1%, 0.063 W, AEC-Q200 Grade 0, 0402", Manufacturer=Vishay-Dale, Power_W=63mW, Supplier Part Number 1=541-10.0KLCT-ND, TempCo="100 ppm/C", Tolerance_%=1%, Value2=0.063W, Value_Code=10k0, ValueDisplayed=10.0k
R11: library part CMP-0097070-1, "Res Thick Film 0402 0 Ohm Jumper Molded SMD Paper T/R", Digikey Part Number=RMCF0402ZT0R00CT-ND, Manufacturer=Stackpole, Operating Temperature Range="-55°C to +155°C", Power=63mW
R12: library part CMP-0026822-3, "RES, 0, 5%, 0.063 W, AEC-Q200 Grade 0, 0402", Manufacturer=Vishay-Dale, Power_W=63mW, Supplier Part Number 1=541-0.0JCT-ND, TempCo="200 ppm/C", Tolerance_%=5%, Value2=0.063W, Value_Code=0000, ValueDisplayed=0
R13: library part CMP-0025963-3, "RES, 10.0, 1%, 0.063 W, AEC-Q200 Grade 0, 0402", Manufacturer=Vishay-Dale, Power_W=63mW, Supplier Part Number 1=541-10.0LCT-ND, TempCo="100 ppm/C", Tolerance_%=1%, Value2=0.063W, Value_Code=10R0, ValueDisplayed=10.0
R14: library part CMP-0026162-2, "RES, 20.0 k, 1%, 0.063 W, AEC-Q200 Grade 0, 0402", Manufacturer=Vishay-Dale, Power_W=63mW, Supplier Part Number 1=541-20.0KLCT-ND, TempCo="100 ppm/C", Tolerance_%=1%, Value2=0.063W, Value_Code=20k0, ValueDisplayed=20.0k
R15: library part CMP-0026298-2, "RES, 33.2 k, 1%, 0.063 W, AEC-Q200 Grade 0, 0402", Manufacturer=Vishay-Dale, Power_W=63mW, Supplier Part Number 1=541-33.2KLCT-ND, TempCo="100 ppm/C", Tolerance_%=1%, Value2=0.063W, Value_Code=33k2, ValueDisplayed=33.2k
R16: library part CMP-0026449-2, "RES, 54.9 k, 1%, 0.063 W, AEC-Q200 Grade 0, 0402", Manufacturer=Vishay-Dale, Power_W=63mW, Supplier Part Number 1=541-54.9KLCT-ND, TempCo="100 ppm/C", Tolerance_%=1%, Value2=0.063W, Value_Code=54k9, ValueDisplayed=54.9k
SH-J1 SH-J2: library part CMP-0003677-2, "Shunt, 100mil, Gold plated, Black", Manufacturer="TE Connectivity", Supplier Part Number 1=A26242-ND
TP1 TP2 TP3 TP6: library part CMP-0055162-1, "Test Point, Miniature, SMT", Manufacturer=Keystone, PartNumber=5019, Supplier Part Number 1=36-5019TR-ND
TP4 TP7 TP9 TP10 TP11: library part CMP-0055149-2, "Test Point, Multipurpose, White, TH", Color=White, Manufacturer="Keystone Electronics", PartNumber=5012, Supplier Part Number 1=36-5012-ND
TP5 TP8 TP12: library part CMP-0055148-2, "Test Point, Multipurpose, Black, TH", Color=Black, Manufacturer="Keystone Electronics", PartNumber=5011, Supplier Part Number 1=36-5011-ND
U1: library part CMP-0096365-1, "Cooper Next FCOL Power Module", Manufacturer="Texas Instruments", Max Supply Voltage=36V, Min Supply Voltage=3V, Nominal Supply Current=1.2uA, Operating Temperature Range="-40°C to +125°C", Output Voltage=5/1-15V, Switching Frequency=1MHz
ZZ1: library part CMP-0003616-3
ZZ2: library part CMP-0077236-1
ZZ3: library part CMP-0077237-1
ZZ4: library part CMP-0077238-1

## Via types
v1: diameter 22, hole 8, Top Layer to Bottom Layer, tented both sides, 61 vias
v2: diameter 19.68, hole 7.87, Top Layer to Bottom Layer, tented both sides, 3 vias
v3: diameter 15.75, hole 7.87, Top Layer to Bottom Layer, tented both sides, 2 vias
